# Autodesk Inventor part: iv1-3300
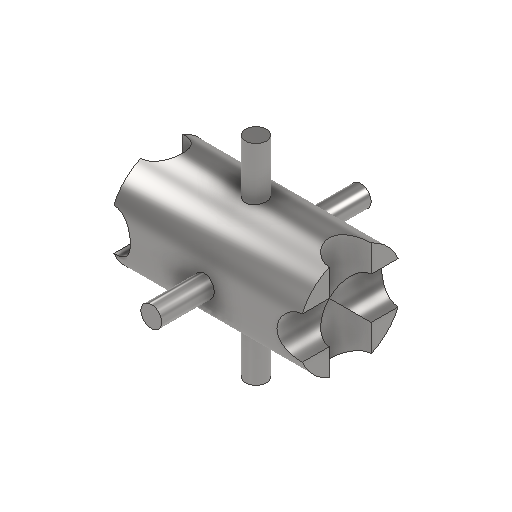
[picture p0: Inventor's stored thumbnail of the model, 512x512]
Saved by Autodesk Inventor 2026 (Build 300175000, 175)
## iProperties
Created: 2022-01
Part Number: iv1-3300
Material: Steel, Mild
Document SubType Name: Modeling
Designer: Lars Bertram Pedersen
Density: 7.85 g/cm^3
Appearance: Semi-Polished
Mass: 1249.49 g
Surface Area: 212.815 cm^2
Volume: 159.17 cm^3
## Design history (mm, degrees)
revolve "Revolution1" stored, may be unused: angle "d2" = 90 deg
sketch "Sketch2"
  geometry: C1 r 5 at (0, 0); 1 further point
  constraints: 1 centre point, 1 coincident
  dimensions: "d3" = 10 diameter of C1
extrude "Extrusion1" join sketch "Sketch2" stored distance "d4" = 100; taper "d5" = 0 deg
sketch "Sketch3"
  geometry: C1 r 5 at (0, 0); 1 further point
  constraints: 1 centre point, 1 coincident
  dimensions: "d6" = 10 diameter of C1
extrude "Extrusion2" join sketch "Sketch3" stored distance "d7" = 100; taper "d8" = 0 deg
sketch "Sketch4"
  geometry: L1 (45, 25)-(45, -25) reference; L2 (-45, 25)-(-45, -25) reference; C1 r 10 at (45, 0); C2 r 10 at (-45, 0); 1 further point
  constraints: 2 centre point, 2 midpoint, 1 equal radius
  dimensions: "d9" = 20 diameter of C1
extrude "Extrusion3" cut sketch "Sketch4" extent not by distance; stored distance "d10" = 0; taper "d11" = 0 deg
sketch "Sketch6"
  geometry: L1 (-45, 22.913)-(-45, -22.913) reference; L2 (45, -22.913)-(45, 22.913) reference; C1 r 10 at (-45, 0); C2 r 10 at (45, 0); 1 further point
  constraints: 2 centre point, 2 midpoint, 1 equal radius
  dimensions: "d12" = 20 diameter of C1
extrude "Extrusion4" cut sketch "Sketch6" extent not by distance; stored distance "d13" = 0; taper "d14" = 0 deg
body "Solid1"
sketch "Sketch1"
  geometry: L1 (-45, 0)-(45, 0); L2 (-45, 0)-(-45, 25); L3 (-45, 25)-(45, 25); L4 (45, 25)-(45, 0); 2 further points
  constraints: 8 end point, 2 perpendicular, 1 coincident, 1 horizontal, 1 midpoint, 1 vertical
  dimensions: "d0" = 90 distance of L1.start L1.end; "d1" = 50 diameter of L3 L1
